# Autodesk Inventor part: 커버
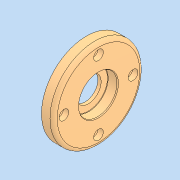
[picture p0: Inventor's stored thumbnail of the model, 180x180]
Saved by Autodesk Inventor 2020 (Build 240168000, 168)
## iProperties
Created: 2024-11
Part Number: 커버
Material: 알루미늄 6061
Document SubType Name: Modeling
Designer: 1강의실14
Density: 2.7 g/cm^3
Appearance: 기본값
Author: jhkim
Sending System: Autodesk Inventor 2025
Preprocessor: ST-DEVELOPER v20
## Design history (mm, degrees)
node "커버1"
node "솔리드2"
node "솔리드1"
